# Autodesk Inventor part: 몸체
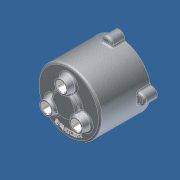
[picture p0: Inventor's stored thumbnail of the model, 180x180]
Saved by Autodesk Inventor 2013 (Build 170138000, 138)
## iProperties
Company: 한국ATC센터
Created: 2014-07
Part Number: 몸체
Document SubType Name: 모델링
Designer: KYOUNG IL JANG
Material: 일반
변환 표준: STEP AP214IS
파일 이름: C:\Users\SeoGD\Desktop\?쒗뿕\紐몄껜.stp
전처리기: Build: 253, Release: 2010 SP1 - Date: Wed 07/29/2009
전송 단위: 밀리미터
불확실성: 0.01
Author: KYOUNG IL JANG
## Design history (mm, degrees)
sketch "스케치2"
  geometry: C1 r 50 at (0, 0); 1 further point
  constraints: 1 centre point, 1 coincident
  dimensions: "d9" = 100 diameter of C1
extrude "돌출2" new body sketch "스케치2" distance "d10" = 80; taper "d11" = 0 deg
feature "쉘1" dims "d12" = 5
sketch "스케치3" dims "d13" = 55
  geometry: C1 r 7.5 at (0, 27.5); C2 r 12.5 at (0, 27.5); 2 further points
  constraints: 2 centre point, 2 coincident, 2 vertical alignment, 2 other
  dimensions: "d14" = 15 diameter of C1; "d15" = 25 diameter of C2
extrude "돌출3" join sketch "스케치3" distance "d16" = 12; taper "d17" = -10 deg
hole "구멍2" diameter "d20" = 15; stored, may be unused: countersink angle "d24" = 90 deg, drill point angle "d26" = 118 deg; dims "d18" = 10, "d19" = 10, "d21" = 6, "d22" = 4, "d23" = 2, "d25" = 15
chamfer "모따기1" distance "d27" = 1; stored, may be unused: second distance "d28" = 2, angle "d29" = 45 deg
sketch "스케치4"
  geometry: L1 (0, 0)-(0, 88); L2 (0, 70)-(13.16, 70); L3 (-45, 75)-(45, 75) reference; L4 (-50, 80)-(50, 80) reference; L5 (13.16, 70)-(14.5, 75); L6 (20, 80)-(20, 88); L7 (20, 88)-(0, 88); L8 (20, 80)-(14.5, 75)
  constraints: 12 end point, 3 point on line, 2 perpendicular, 1 vertical
  dimensions: "d34" = 40 diameter of L6 L1; "d35" = 105 deg angle of L5 L3; "d36" = 5 distance between parallel lines of L2 L3; "d37" = 8 distance between parallel lines of L7 L4; "d51" = 29 diameter of L5.end L1
revolve "회전1" sketch "스케치4" stored, may be unused: angle "d38" = 90 deg
hole "구멍3" diameter "d41" = 15; stored, may be unused: countersink angle "d45" = 90 deg, drill point angle "d47" = 0 deg; dims "d39" = 10, "d40" = 10, "d42" = 6, "d43" = 22, "d44" = 13, "d46" = 15
chamfer "모따기2" distance "d48" = 1; stored, may be unused: second distance "d49" = 2, angle "d50" = 45 deg
fillet "모깎기1" dims "d52" = 3
fillet "모깎기2" dims "d53" = 3, "d72" = 0.2
sketch "스케치5"
  geometry: A1 r 50 centre (0, 0) between (50, 0) and (-8.074, 49.344) reference; A2 r 8.5 centre (0, 52) between (8.074, 49.344) and (-8.074, 49.344); 1 further point
  constraints: 5 point on circle, 1 centre point, 1 horizontal alignment
  dimensions: "d54" = 90 deg dimension on point (0, 0) A2.centre A1.start; "d55" = 52 distance of A2.centre point (0, 0); "d56" = 17 diameter of A2
extrude "돌출4" join sketch "스케치5" distance "d57" = 20; taper "d58" = 0 deg
fillet "모깎기3" dims "d59" = 3
hole "구멍4" diameter "d62" = 4.134; stored, may be unused: countersink angle "d66" = 90 deg, drill point angle "d68" = 118 deg; dims "d60" = 10, "d61" = 10, "d63" = 12, "d64" = 22, "d65" = 13, "d67" = 15
sketch "스케치6"
  geometry: C1 r 47 at (0, 0) reference; C2 r 42.5 at (0, 0); 1 further point
  constraints: 1 centre point, 1 coincident, 1 other
  dimensions: "d73" = 85 diameter of C2
feature "엠보싱1" sketch "스케치6" dims "d74" = 1, "d75" = 0
node "솔리드1"
node "솔리드 본체"
node "곡면 본체"
pattern_circular "원형 패턴1" dims "d31" = 360 deg
pattern_circular "원형 패턴2" dims "d70" = 360 deg
node "솔리드2"
